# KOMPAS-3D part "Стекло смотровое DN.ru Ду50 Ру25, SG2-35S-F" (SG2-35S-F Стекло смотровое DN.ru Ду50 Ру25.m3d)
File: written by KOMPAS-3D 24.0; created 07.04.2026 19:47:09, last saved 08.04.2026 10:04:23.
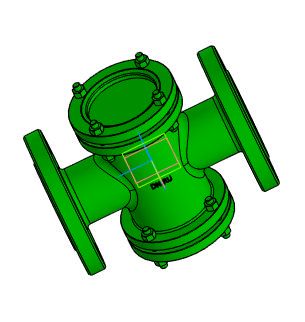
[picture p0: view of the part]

Document properties: Автор: Main; Полное имя файла: SG2-34G-FСтекло смотровое DN.ru Ду50 Ру40 (3d).cdw

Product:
- Body: Тело 1  | qty 1
    Масса: 11.518228
- Part/product: Стекло смотровое DN.ru Ду50 Ру25  | designation SG2-35S-F
    Масса: 10.5
    Раздел спецификации: Прочие изделия
    Форматы листов документа: A4
    Примечание: D500-00096

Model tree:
1. Операция без истории:1

Expressions: SG2-35S-F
